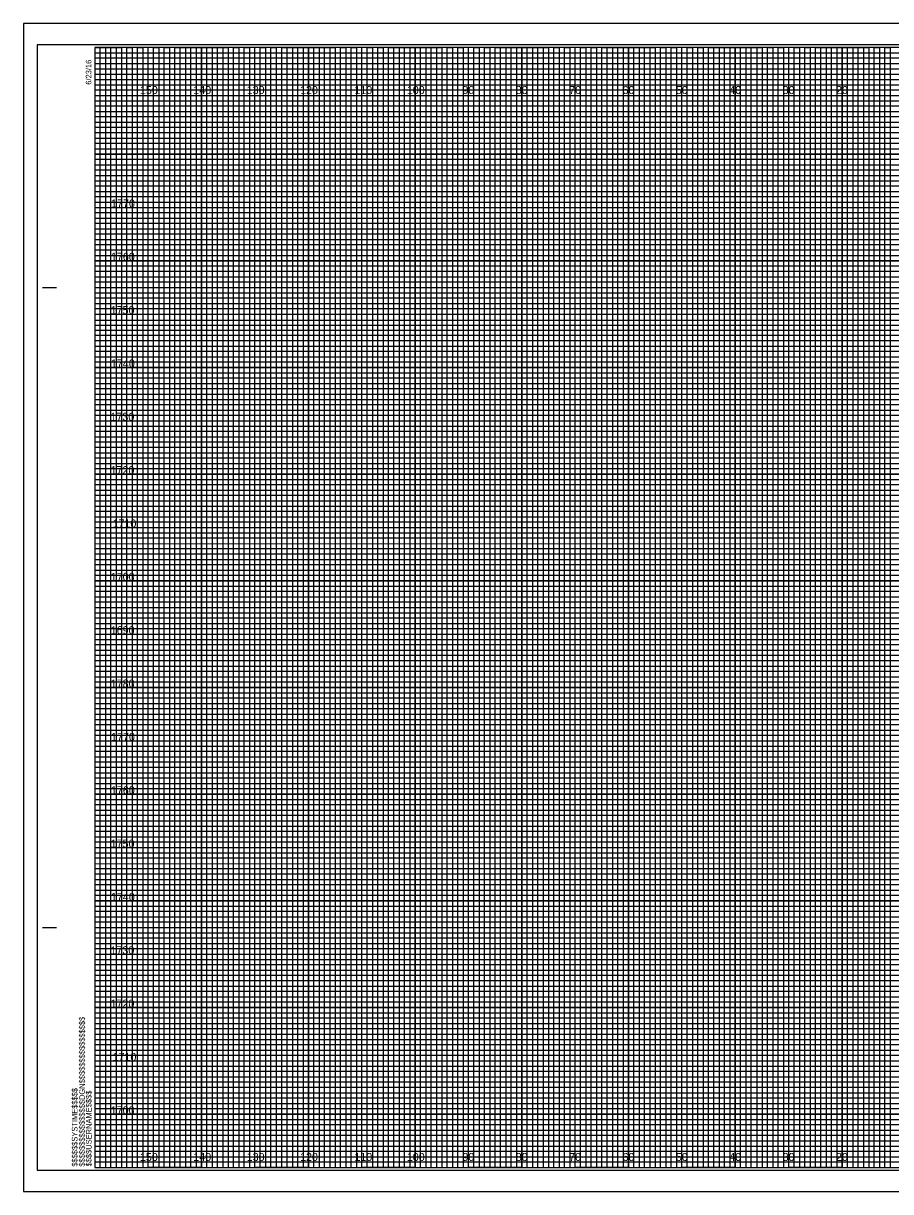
# Model space of a CAD drawing. Extents: x 185 to 522, y -7 to 872.
# Drawn here: x 184.8 to 347.3, y 653.5 to 872.5 of the extents above; entities that cross this region are included whole.
import ezdxf

# ---------------------------------------------------------------- set-up
doc = ezdxf.new("R2010")
doc.units = 0
for name, color, linetype in [('Raster_Level_0', 7, 'Continuous'), ('Scratch_Level_3', 7, 'Continuous'), ('Sheet Cross Section CELL', 7, 'Continuous'), ('Sheet Cross Section Grid Major CELL', 7, 'Continuous'), ('Sheet Cross Section Grid Middle CELL', 7, 'Continuous'), ('Sheet Cross Section Grid Minor 1 CELL', 7, 'Continuous'), ('Sheet Cross Section Grid Minor 2 CELL', 7, 'Continuous'), ('Sheet Cutting Line CELL', 7, 'Continuous'), ('Sheet DOT Grid CELL', 7, 'Continuous'), ('Sheet Plot Border Inside CELL', 7, 'Continuous'), ('Sheet Plot Border Outside CELL', 7, 'Continuous')]:
    doc.layers.add(name, color=color, linetype=linetype)

msp = doc.modelspace()

# ---------------------------------------------------------------- linework, layer by layer
at = {"layer": 'Sheet Cross Section CELL'}
for p, q in [((188.44, 822.95), (190.94, 822.95)), ((188.54, 822.95), (191.04, 822.95)), ((188.44, 702.95), (190.94, 702.95)), ((188.54, 702.95), (191.04, 702.95)), ((198.24, 657.95), (198.24, 657.95)), ((198.24, 657.95), (198.24, 657.95)), ((198.24, 657.95), (198.24, 657.95)), ((198.24, 657.95), (198.24, 657.95)), ((198.24, 657.95), (198.24, 657.95)), ((198.24, 657.95), (198.24, 657.95)), ((198.24, 657.95), (198.24, 657.95))]:
    msp.add_line(p, q, dxfattribs=at)
msp.add_lwpolyline([(518.24, 867.95), (198.24, 867.95), (198.24, 657.95), (518.24, 657.95)], close=True, dxfattribs=at)
at = {"layer": 'Sheet Cross Section Grid Major CELL'}
for p, q in [((208.24, 867.95), (198.24, 867.95)), ((208.24, 657.95), (208.24, 867.95)), ((228.24, 867.95), (218.24, 867.95)), ((218.24, 867.95), (218.24, 657.95)), ((228.24, 657.95), (228.24, 867.95)), ((248.24, 867.95), (238.24, 867.95)), ((238.24, 867.95), (238.24, 657.95)), ((248.24, 657.95), (248.24, 867.95)), ((268.24, 867.95), (258.24, 867.95)), ((258.24, 867.95), (258.24, 657.95)), ((268.24, 657.95), (268.24, 867.95)), ((288.24, 867.95), (278.24, 867.95)), ((278.24, 867.95), (278.24, 657.95)), ((288.24, 657.95), (288.24, 867.95)), ((308.24, 867.95), (298.24, 867.95)), ((298.24, 867.95), (298.24, 657.95)), ((308.24, 657.95), (308.24, 867.95)), ((328.24, 867.95), (318.24, 867.95)), ((318.24, 867.95), (318.24, 657.95)), ((328.24, 657.95), (328.24, 867.95)), ((348.24, 867.95), (338.24, 867.95)), ((338.24, 867.95), (338.24, 657.95)), ((218.24, 657.95), (208.24, 657.95)), ((238.24, 657.95), (228.24, 657.95)), ((258.24, 657.95), (248.24, 657.95)), ((278.24, 657.95), (268.24, 657.95)), ((298.24, 657.95), (288.24, 657.95)), ((318.24, 657.95), (308.24, 657.95)), ((338.24, 657.95), (328.24, 657.95))]:
    msp.add_line(p, q, dxfattribs=at)
for points in [[(198.24, 857.95), (518.24, 857.95), (518.24, 847.95), (198.24, 847.95)], [(198.24, 837.95), (518.24, 837.95), (518.24, 827.95), (198.24, 827.95)], [(198.24, 817.95), (518.24, 817.95), (518.24, 807.95), (198.24, 807.95)], [(198.24, 797.95), (518.24, 797.95), (518.24, 787.95), (198.24, 787.95)], [(198.24, 777.95), (518.24, 777.95), (518.24, 767.95), (198.24, 767.95)], [(198.24, 757.95), (518.24, 757.95), (518.24, 747.95), (198.24, 747.95)], [(198.24, 737.95), (518.24, 737.95), (518.24, 727.95), (198.24, 727.95)], [(198.24, 717.95), (518.24, 717.95), (518.24, 707.95), (198.24, 707.95)], [(198.24, 697.95), (518.24, 697.95), (518.24, 687.95), (198.24, 687.95)], [(198.24, 677.95), (518.24, 677.95), (518.24, 667.95), (198.24, 667.95)]]:
    msp.add_lwpolyline(points, dxfattribs=at)
at = {"layer": 'Sheet Cross Section Grid Middle CELL'}
for points in [[(198.24, 867.95), (203.24, 867.95), (203.24, 657.95), (213.24, 657.95), (213.24, 867.95), (223.24, 867.95), (223.24, 657.95), (233.24, 657.95), (233.24, 867.95), (243.24, 867.95), (243.24, 657.95), (253.24, 657.95), (253.24, 867.95), (263.24, 867.95), (263.24, 657.95), (273.24, 657.95), (273.24, 867.95), (283.24, 867.95), (283.24, 657.95), (293.24, 657.95), (293.24, 867.95), (303.24, 867.95), (303.24, 657.95), (313.24, 657.95), (313.24, 867.95), (323.24, 867.95), (323.24, 657.95), (333.24, 657.95), (333.24, 867.95), (343.24, 867.95), (343.24, 657.95), (353.24, 657.95)], [(198.24, 862.95), (473.24, 862.95)], [(198.24, 842.95), (518.24, 842.95), (518.24, 852.95), (198.24, 852.95)], [(198.24, 822.95), (518.24, 822.95), (518.24, 832.95), (198.24, 832.95)], [(198.24, 802.95), (518.24, 802.95), (518.24, 812.95), (198.24, 812.95)], [(198.24, 782.95), (518.24, 782.95), (518.24, 792.95), (198.24, 792.95)], [(198.24, 762.95), (518.24, 762.95), (518.24, 772.95), (198.24, 772.95)], [(198.24, 742.95), (518.24, 742.95), (518.24, 752.95), (198.24, 752.95)], [(198.24, 722.95), (518.24, 722.95), (518.24, 732.95), (198.24, 732.95)], [(198.24, 702.95), (518.24, 702.95), (518.24, 712.95), (198.24, 712.95)], [(198.24, 682.95), (518.24, 682.95), (518.24, 692.95), (198.24, 692.95)], [(198.24, 662.95), (518.24, 662.95), (518.24, 672.95), (198.24, 672.95)]]:
    msp.add_lwpolyline(points, dxfattribs=at)
at = {"layer": 'Sheet Cross Section Grid Minor 1 CELL'}
for p, q in [((198.24, 866.95), (458.24, 866.95)), ((458.24, 865.93), (198.24, 865.93)), ((198.24, 865.93), (198.24, 864.95)), ((198.24, 864.95), (458.24, 864.95)), ((458.24, 863.84), (198.24, 863.84)), ((198.24, 863.84), (198.24, 861.95)), ((198.24, 861.95), (518.24, 861.95))]:
    msp.add_line(p, q, dxfattribs=at)
for points in [[(198.24, 860.95), (468.24, 860.95), (518.24, 860.95), (518.24, 859.95), (198.24, 859.95)], [(198.24, 858.95), (518.24, 858.95), (518.24, 856.95), (198.24, 856.95)], [(198.24, 855.95), (518.24, 855.95), (518.24, 854.95), (198.24, 854.93)], [(198.24, 853.95), (518.24, 853.95), (518.24, 851.95), (198.24, 851.95)], [(198.24, 850.95), (518.24, 850.95), (518.24, 849.95), (198.24, 849.95)], [(198.24, 848.95), (518.24, 848.95), (518.24, 846.95), (198.24, 846.95)], [(198.24, 845.95), (518.24, 845.95), (518.24, 844.95), (198.24, 844.95)], [(198.24, 843.95), (518.24, 843.95), (518.24, 841.95), (198.24, 841.95)], [(198.24, 840.95), (518.24, 840.95), (518.24, 839.95), (198.24, 839.95)], [(198.24, 838.95), (518.24, 838.95), (518.24, 836.95), (198.24, 836.95)], [(198.24, 835.95), (518.24, 835.95), (518.24, 834.95), (198.24, 834.95)], [(198.24, 833.95), (518.24, 833.95), (518.24, 831.9), (518.24, 830.95), (518.24, 829.95), (198.24, 829.95)], [(198.24, 831.95), (518.24, 831.95), (518.24, 830.95), (198.24, 830.95)], [(198.24, 828.95), (518.24, 828.95), (518.24, 826.95), (198.24, 826.98)], [(198.24, 826.98), (518.24, 826.95), (518.24, 825.95), (198.24, 825.95)], [(198.24, 824.95), (518.24, 824.95), (518.24, 823.95), (198.24, 823.95)], [(198.24, 821.95), (518.24, 821.95), (518.24, 820.95), (198.24, 820.95)], [(198.24, 819.95), (518.24, 819.95), (518.24, 818.95), (198.24, 818.95)], [(198.17, 816.84), (518.24, 816.84), (518.24, 815.83), (198.17, 815.83)], [(198.24, 814.95), (518.24, 814.95), (518.24, 813.95), (198.24, 813.95)], [(198.24, 811.95), (518.24, 811.95), (518.24, 810.95), (198.24, 810.95)], [(198.24, 809.95), (518.24, 809.95), (518.24, 808.95), (198.24, 808.95)], [(198.24, 806.95), (518.24, 806.95), (518.24, 805.95), (198.24, 805.95)], [(198.24, 804.95), (518.24, 804.95), (518.24, 803.95), (198.24, 803.95)], [(198.24, 801.95), (518.24, 801.95), (518.24, 800.95), (198.24, 800.95)], [(198.24, 799.95), (518.24, 799.95), (518.24, 798.95), (198.24, 798.95)], [(198.24, 796.95), (518.24, 796.95), (518.23, 795.93), (198.24, 795.95)], [(198.24, 794.95), (518.24, 794.95), (518.24, 793.95), (198.24, 793.95)], [(198.24, 791.95), (518.24, 791.95), (518.24, 790.95), (198.24, 790.95)], [(198.24, 789.95), (518.24, 789.95), (518.24, 788.95), (198.24, 788.95)], [(198.24, 786.95), (518.24, 786.95), (518.24, 785.95), (198.24, 785.95)], [(198.24, 784.95), (518.24, 784.95), (518.24, 783.95), (198.24, 783.95)], [(198.24, 781.95), (518.24, 781.95), (518.24, 780.95), (198.24, 780.95)], [(198.24, 779.95), (518.24, 779.95), (518.24, 778.95), (198.24, 778.95)], [(198.24, 776.95), (518.24, 776.95), (518.24, 775.95), (198.24, 775.95)], [(198.24, 774.94), (518.31, 774.86), (518.24, 773.95), (198.24, 773.95)], [(198.24, 771.95), (518.24, 771.95), (518.24, 770.95), (198.24, 770.95)], [(198.24, 769.95), (518.24, 769.95), (518.24, 768.95), (198.24, 768.95)], [(198.24, 766.95), (518.24, 766.95), (518.24, 765.95), (198.24, 765.95)], [(198.24, 764.95), (518.24, 764.95), (518.24, 763.95), (198.24, 763.95)], [(198.24, 761.95), (518.24, 761.95), (518.24, 760.95), (198.24, 760.95)], [(198.24, 759.95), (518.24, 759.95), (518.24, 758.95), (198.24, 758.95)], [(198.24, 756.95), (518.24, 756.95), (518.24, 755.95), (198.24, 755.95)], [(198.24, 754.95), (518.24, 754.95), (518.24, 753.95), (198.24, 753.95)], [(198.24, 751.95), (518.24, 751.95), (518.24, 750.95), (198.24, 750.95)], [(198.24, 749.95), (518.24, 749.95), (518.24, 748.95), (198.24, 748.95)], [(198.24, 746.95), (518.24, 746.95), (518.24, 745.95), (198.24, 745.95)], [(198.24, 744.95), (518.24, 744.95), (518.24, 743.95), (198.24, 743.95)], [(198.24, 741.95), (518.24, 741.95), (518.24, 740.95), (198.24, 740.95)], [(198.24, 739.95), (518.24, 739.95), (518.24, 738.95), (198.24, 738.95)], [(198.24, 736.95), (518.24, 736.95), (518.23, 735.93), (198.24, 735.95)], [(198.24, 734.95), (518.24, 734.95), (518.24, 733.95), (198.24, 733.95)], [(198.24, 731.95), (518.24, 731.95), (518.24, 730.95), (198.24, 730.95)], [(198.24, 729.95), (518.24, 729.95), (518.24, 728.95), (198.24, 728.95)], [(198.24, 726.95), (518.24, 726.95), (518.24, 725.95), (198.24, 725.95)], [(198.24, 724.95), (518.24, 724.95), (518.24, 723.95), (198.24, 723.95)], [(198.24, 721.95), (518.24, 721.95), (518.24, 720.95), (198.24, 720.95)], [(198.24, 719.95), (518.24, 719.95), (518.24, 718.95), (198.24, 718.95)], [(198.24, 716.95), (518.24, 716.95), (518.24, 715.95), (198.24, 715.95)], [(198.24, 714.94), (518.31, 714.86), (518.24, 713.95), (198.24, 713.95)], [(198.24, 711.95), (518.24, 711.95), (518.24, 710.95), (198.24, 710.95)], [(198.24, 709.95), (518.24, 709.95), (518.24, 708.95), (198.24, 708.95)], [(198.24, 706.95), (518.24, 706.95), (518.24, 705.95), (198.24, 705.95)], [(198.24, 704.95), (518.24, 704.95), (518.24, 703.95), (198.24, 703.95)], [(198.24, 701.95), (518.24, 701.95), (518.24, 700.95), (198.24, 700.95)], [(198.24, 699.95), (518.24, 699.95), (518.24, 698.95), (198.24, 698.95)], [(198.24, 696.95), (518.24, 696.95), (518.24, 695.95), (198.24, 695.95)], [(198.24, 694.95), (518.24, 694.95), (518.24, 693.95), (198.24, 693.95)], [(198.24, 691.95), (518.24, 691.95), (518.24, 690.95), (198.24, 690.95)], [(198.24, 689.95), (518.24, 689.95), (518.24, 688.95), (198.24, 688.95)], [(198.24, 686.95), (518.24, 686.95), (518.24, 685.95), (198.24, 685.95)], [(198.24, 684.95), (518.24, 684.95), (518.24, 683.95), (198.24, 683.95)], [(198.24, 681.95), (518.24, 681.95), (518.24, 680.95), (198.24, 680.95)], [(198.24, 679.95), (518.24, 679.95), (518.24, 678.95), (198.24, 678.95)], [(198.24, 676.95), (518.24, 676.95), (518.24, 675.95), (198.24, 675.95)], [(198.24, 674.95), (518.24, 674.95), (518.24, 673.95), (198.24, 673.95)], [(198.24, 671.95), (518.24, 671.95), (518.24, 670.95), (198.24, 670.95)], [(198.24, 669.95), (518.24, 669.95), (518.24, 668.95), (198.24, 668.95)], [(198.24, 666.95), (518.24, 666.95), (518.24, 665.95), (198.24, 665.95)], [(198.24, 664.95), (518.24, 664.95), (518.24, 663.95), (198.24, 663.95)], [(198.24, 661.95), (518.24, 661.95), (518.24, 660.95), (198.24, 660.95)], [(198.24, 659.95), (518.24, 659.95), (518.24, 658.95), (198.24, 658.95)]]:
    msp.add_lwpolyline(points, dxfattribs=at)
at = {"layer": 'Sheet Cross Section Grid Minor 2 CELL'}
for points in [[(198.24, 657.95), (199.24, 657.95), (199.24, 867.95), (200.24, 867.95), (200.24, 657.95)], [(200.24, 657.95), (201.24, 657.95), (201.24, 867.95), (202.24, 867.95), (202.24, 657.95)], [(203.24, 657.95), (204.24, 657.95), (204.24, 867.95), (205.24, 867.95), (205.24, 657.95)], [(205.24, 657.95), (206.24, 657.95), (206.24, 867.95), (207.24, 867.95), (207.24, 657.95)], [(208.24, 657.95), (209.24, 657.95), (209.24, 867.95), (210.24, 867.95), (210.24, 657.95)], [(210.24, 657.95), (211.24, 657.95), (211.24, 867.95), (212.24, 867.95), (212.24, 657.95)], [(213.24, 657.95), (214.24, 657.95), (214.24, 867.95), (215.24, 867.95), (215.24, 657.95)], [(215.24, 657.95), (216.24, 657.95), (216.24, 867.95), (217.24, 867.95), (217.24, 657.95)], [(218.24, 657.95), (219.24, 657.95), (219.24, 867.95), (220.24, 867.95), (220.24, 657.95)], [(220.24, 657.95), (221.24, 657.95), (221.24, 867.95), (222.24, 867.95), (222.24, 657.95)], [(223.24, 657.95), (224.24, 657.95), (224.24, 867.95), (225.24, 867.95), (225.24, 657.95)], [(225.24, 657.95), (226.24, 657.95), (226.24, 867.95), (227.24, 867.95), (227.24, 657.95)], [(228.24, 657.95), (229.24, 657.95), (229.24, 867.95), (230.24, 867.95), (230.24, 657.95)], [(230.24, 657.95), (231.24, 657.95), (231.24, 867.95), (232.24, 867.95), (232.24, 657.95)], [(233.24, 657.95), (234.24, 657.95), (234.24, 867.95), (235.24, 867.95), (235.24, 657.95)], [(235.24, 657.95), (236.24, 657.95), (236.24, 867.95), (237.24, 867.95), (237.24, 657.95)], [(238.24, 657.95), (239.24, 657.95), (239.24, 867.95), (240.24, 867.95), (240.24, 657.95)], [(240.24, 657.95), (241.24, 657.95), (241.24, 867.95), (242.24, 867.95), (242.24, 657.95)], [(243.24, 657.95), (244.24, 657.95), (244.24, 867.95), (245.24, 867.95), (245.24, 657.95)], [(245.24, 657.95), (246.24, 657.95), (246.24, 867.95), (247.24, 867.95), (247.24, 657.95)], [(248.24, 657.95), (249.24, 657.95), (249.24, 867.95), (250.24, 867.95), (250.24, 657.95)], [(250.24, 657.95), (251.24, 657.95), (251.24, 867.95), (252.24, 867.95), (252.24, 657.95)], [(253.24, 657.95), (254.24, 657.95), (254.24, 867.95), (255.24, 867.95), (255.24, 657.95)], [(255.24, 657.95), (256.24, 657.95), (256.24, 867.95), (257.24, 867.95), (257.24, 657.95)], [(258.24, 657.95), (259.24, 657.95), (259.24, 867.95), (260.24, 867.95), (260.24, 657.95)], [(260.24, 657.95), (261.24, 657.95), (261.24, 867.95), (262.24, 867.95), (262.24, 657.95)], [(263.24, 657.95), (264.24, 657.95), (264.24, 867.95), (265.24, 867.95), (265.24, 657.95)], [(265.24, 657.95), (266.24, 657.95), (266.24, 867.95), (267.24, 867.95), (267.24, 657.95)], [(268.24, 657.95), (269.24, 657.95), (269.24, 867.95), (270.24, 867.95), (270.24, 657.95)], [(270.24, 657.95), (271.24, 657.95), (271.24, 867.95), (272.24, 867.95), (272.24, 657.95)], [(273.24, 657.95), (274.24, 657.95), (274.24, 867.95), (275.24, 867.95), (275.24, 657.95)], [(275.24, 657.95), (276.24, 657.95), (276.24, 867.95), (277.24, 867.95), (277.24, 657.95)], [(278.24, 657.95), (279.24, 657.95), (279.24, 867.95), (280.24, 867.95), (280.24, 657.95)], [(280.24, 657.95), (281.24, 657.95), (281.24, 867.95), (282.24, 867.95), (282.24, 657.95)], [(283.24, 657.95), (284.24, 657.95), (284.24, 867.95), (285.24, 867.95), (285.24, 657.95)], [(285.24, 657.95), (286.24, 657.95), (286.24, 867.95), (287.24, 867.95), (287.24, 657.95)], [(288.24, 657.95), (289.24, 657.95), (289.24, 867.95), (290.24, 867.95), (290.24, 657.95)], [(290.24, 657.95), (291.24, 657.95), (291.24, 867.95), (292.24, 867.95), (292.24, 657.95)], [(293.24, 657.95), (294.24, 657.95), (294.24, 867.95), (295.24, 867.95), (295.24, 657.95)], [(295.24, 657.95), (296.24, 657.95), (296.24, 867.95), (297.24, 867.95), (297.24, 657.95)], [(298.24, 657.95), (299.24, 657.95), (299.24, 867.95), (300.24, 867.95), (300.24, 657.95)], [(300.24, 657.95), (301.24, 657.95), (301.24, 867.95), (302.24, 867.95), (302.24, 657.95)], [(303.24, 657.95), (304.24, 657.95), (304.24, 867.95), (305.24, 867.95), (305.24, 657.95)], [(305.24, 657.95), (306.24, 657.95), (306.24, 867.95), (307.24, 867.95), (307.24, 657.95)], [(308.24, 657.95), (309.24, 657.95), (309.24, 867.95), (310.24, 867.95), (310.24, 657.95)], [(310.24, 657.95), (311.24, 657.95), (311.24, 867.95), (312.24, 867.95), (312.24, 657.95)], [(313.24, 657.95), (314.24, 657.95), (314.24, 867.95), (315.24, 867.95), (315.24, 657.95)], [(315.24, 657.95), (316.24, 657.95), (316.24, 867.95), (317.24, 867.95), (317.24, 657.95)], [(318.24, 657.95), (319.24, 657.95), (319.24, 867.95), (320.24, 867.95), (320.24, 657.95)], [(320.24, 657.95), (321.24, 657.95), (321.24, 867.95), (322.24, 867.95), (322.24, 657.95)], [(323.24, 657.95), (324.24, 657.95), (324.24, 867.95), (325.24, 867.95), (325.24, 657.95)], [(325.24, 657.95), (326.24, 657.95), (326.24, 867.95), (327.24, 867.95), (327.24, 657.95)], [(328.24, 657.95), (329.24, 657.95), (329.24, 867.95), (330.24, 867.95), (330.24, 657.95)], [(330.24, 657.95), (331.24, 657.95), (331.24, 867.95), (332.24, 867.95), (332.24, 657.95)], [(333.24, 657.95), (334.24, 657.95), (334.24, 867.95), (335.24, 867.95), (335.24, 657.95)], [(335.24, 657.95), (336.24, 657.95), (336.24, 867.95), (337.24, 867.95), (337.24, 657.95)], [(338.24, 657.95), (339.24, 657.95), (339.24, 867.95), (340.24, 867.95), (340.24, 657.95)], [(340.24, 657.95), (341.24, 657.95), (341.24, 867.95), (342.24, 867.95), (342.24, 657.95)], [(343.24, 657.95), (344.24, 657.95), (344.24, 867.95), (345.24, 867.95), (345.24, 657.95)], [(345.24, 657.95), (346.24, 657.95), (346.24, 867.95), (347.24, 867.95), (347.24, 657.95)]]:
    msp.add_lwpolyline(points, dxfattribs=at)
at = {"layer": 'Sheet Cutting Line CELL'}
for p, q in [((521.54, 872.45), (184.84, 872.45)), ((184.84, 872.45), (184.84, 653.45)), ((184.84, 653.45), (521.54, 653.45))]:
    msp.add_line(p, q, dxfattribs=at)
at = {"layer": 'Sheet DOT Grid CELL'}
for p, q in [((208.24, 657.95), (208.24, 867.95)), ((218.24, 657.95), (218.24, 867.95)), ((228.24, 657.95), (228.24, 867.95)), ((238.24, 657.95), (238.24, 867.95)), ((248.24, 657.95), (248.24, 867.95)), ((258.24, 657.95), (258.24, 867.95)), ((268.24, 657.95), (268.24, 867.95)), ((278.24, 657.95), (278.24, 867.95)), ((288.24, 657.95), (288.24, 867.95)), ((298.24, 657.95), (298.24, 867.95)), ((308.24, 657.95), (308.24, 867.95)), ((318.24, 657.95), (318.24, 867.95)), ((328.24, 657.95), (328.24, 867.95)), ((338.24, 657.95), (338.24, 867.95)), ((198.24, 857.95), (518.24, 857.95)), ((198.24, 847.95), (518.24, 847.95)), ((198.24, 837.95), (518.24, 837.95)), ((198.24, 827.95), (518.24, 827.95)), ((198.24, 817.95), (518.24, 817.95)), ((198.24, 807.95), (518.24, 807.95)), ((198.24, 797.95), (518.24, 797.95)), ((198.24, 787.95), (518.24, 787.95)), ((198.24, 777.95), (518.24, 777.95)), ((198.24, 767.95), (518.24, 767.95)), ((198.24, 757.95), (518.24, 757.95)), ((198.24, 747.95), (518.24, 747.95)), ((198.24, 737.95), (518.24, 737.95)), ((198.24, 727.95), (518.24, 727.95)), ((198.24, 717.95), (518.24, 717.95)), ((198.24, 707.95), (518.24, 707.95)), ((198.24, 697.95), (518.24, 697.95)), ((198.24, 687.95), (518.24, 687.95)), ((198.24, 677.95), (518.24, 677.95)), ((198.24, 667.95), (518.24, 667.95))]:
    msp.add_line(p, q, dxfattribs=at)
at = {"layer": 'Sheet Plot Border Inside CELL'}
msp.add_lwpolyline([(187.44, 657.45), (520.64, 657.45), (520.64, 868.45), (187.44, 868.45)], close=True, dxfattribs=at)
at = {"layer": 'Sheet Plot Border Outside CELL'}
msp.add_lwpolyline([(184.84, 653.45), (521.54, 653.45), (521.54, 872.45), (184.84, 872.45)], close=True, dxfattribs=at)

# ---------------------------------------------------------------- texts
at = {"layer": 'Raster_Level_0'}
for s, p in [('150', (206.69, 859.2)), ('140', (216.69, 859.2)), ('130', (226.69, 859.2)), ('120', (236.69, 859.2)), ('110', (246.87, 859.2)), ('100', (256.69, 859.2)), ('90', (267.1, 859.2)), ('80', (277.1, 859.2)), ('70', (287.1, 859.2)), ('60', (297.1, 859.2)), ('50', (307.1, 859.2)), ('40', (317.1, 859.2)), ('30', (327.1, 859.2)), ('20', (337.1, 859.2)), ('150', (206.69, 659.2)), ('140', (216.69, 659.2)), ('130', (226.69, 659.2)), ('120', (236.69, 659.2)), ('110', (246.87, 659.2)), ('100', (256.69, 659.2)), ('90', (267.1, 659.2)), ('80', (277.1, 659.2)), ('70', (287.1, 659.2)), ('60', (297.1, 659.2)), ('50', (307.1, 659.2)), ('40', (317.1, 659.2)), ('30', (327.1, 659.2)), ('20', (337.1, 659.2))]:
    msp.add_text(s, height=1.5, dxfattribs=at).set_placement(p)
at = {"layer": 'Scratch_Level_3'}
for s, p in [('1770', (201.28, 837.95)), ('1760', (201.25, 827.95)), ('1750', (201.2, 817.95)), ('1740', (201.25, 807.95)), ('1730', (201.17, 797.95)), ('1720', (201.18, 787.95)), ('1710', (201.55, 777.95)), ('1700', (201.22, 767.95)), ('1690', (201.21, 757.95)), ('1780', (201.22, 747.95)), ('1770', (201.28, 737.95)), ('1760', (201.25, 727.95)), ('1750', (201.2, 717.95)), ('1740', (201.25, 707.95)), ('1730', (201.17, 697.95)), ('1720', (201.18, 687.95)), ('1710', (201.55, 677.95)), ('1700', (201.22, 667.95))]:
    msp.add_text(s, height=1.5, dxfattribs=at).set_placement(p)
at = {"layer": 'Sheet Cross Section CELL'}
for s, p in [('6/23/16', (197.59, 860.95)), ('$$$$$$$$$$$$$$$$DGN$$$$$$$$$$$$$$$$', (196.36, 658.13)), ('$$$$$$SYSTIME$$$$$', (194.98, 658.13)), ('$$$$USERNAME$$$$', (197.62, 658.18))]:
    msp.add_text(s, height=1.05, rotation=90, dxfattribs=at).set_placement(p)

doc.saveas('drawing.dxf')
